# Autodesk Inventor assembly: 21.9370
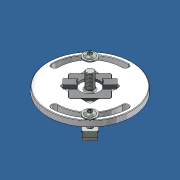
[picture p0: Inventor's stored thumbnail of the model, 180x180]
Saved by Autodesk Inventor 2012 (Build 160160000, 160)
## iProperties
Created: 2013-05
Part Number: 21.9370
Document SubType Name: Assembly
Designer: Admin
Description: PIVOT FASTENER 45
Author: Admin
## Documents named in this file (6)
- C:\Andys Backup Data\ANDY'S INVENTOR\INVENTOR LIBRARIES\PARTS LIBRARY\FASTENING ELEMENTS\21.9370 PIVOT FASTENER 45.iam
- C:\Andys Backup Data\ANDY'S INVENTOR\INVENTOR LIBRARIES\PARTS LIBRARY\FASTENING ELEMENTS\SUBCOMPONENTS\21.2016 ANTI TWIST.ipt
- C:\Andys Backup Data\ANDY'S INVENTOR\INVENTOR LIBRARIES\PARTS LIBRARY\FASTENING ELEMENTS\BUTTON HEAD FLANGE SCREWS\21.9965 M6X20 BUTTON HEAD FLANGE.ipt
- C:\Andys Backup Data\ANDY'S INVENTOR\INVENTOR LIBRARIES\PARTS LIBRARY\FASTENING ELEMENTS\NUTS\21.1330_2 M6 SQUARE NUT POS FXG.ipt
- C:\Andys Backup Data\ANDY'S INVENTOR\INVENTOR LIBRARIES\PARTS LIBRARY\FASTENING ELEMENTS\SUBCOMPONENTS\21.9370_1 PIVOT FASTENER 45.ipt
- C:\Andys Backup Data\ANDY'S INVENTOR\INVENTOR LIBRARIES\PARTS LIBRARY\FASTENING ELEMENTS\SCREWS COUNTERSUNK\21.1514 M8X20 CSUNK.IPT
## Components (7 placed, 5 different names)
1. 21.9370_1 PIVOT FASTENER 45:1 — Flush:1, Mate:1, Mate:2, Flush:2, Mate:5, Mate:6, Mate:12, Mate:13, Mate:14, Mate:15, Angle:4
2. 21.2016 ANTI TWIST:1 — Flush:1, Mate:1, Angle:2, Angle:3, Angle:4, Mate:17
3. 21.1514 M8x20 C'SUNK:1 — Mate:2, Flush:2
4. 21.9965 M6X20 BUTTON HEAD FLANGE:1 — Mate:5, Mate:9, Mate:12
5. 21.9965 M6X20 BUTTON HEAD FLANGE:2 — Mate:6, Mate:11, Mate:13, Mate:16, Mate:17
6. 21.1330_2 M6 SQUARE NUT POS FXG:1 — Mate:9, Mate:15, Angle:3, Mate:16
7. 21.1330_2 M6 SQUARE NUT POS FXG:2 — Mate:11, Angle:2, Mate:14
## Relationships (17: Mate 12, Angle 3, Flush 2)
- Flush:1: 21.9370_1 PIVOT FASTENER 45:1 ↔ 21.2016 ANTI TWIST:1
- Mate:1: 21.9370_1 PIVOT FASTENER 45:1 ↔ 21.2016 ANTI TWIST:1
- Mate:2: 21.9370_1 PIVOT FASTENER 45:1 ↔ 21.1514 M8x20 C'SUNK:1
- Flush:2: 21.9370_1 PIVOT FASTENER 45:1 ↔ 21.1514 M8x20 C'SUNK:1
- Mate:5: 21.9370_1 PIVOT FASTENER 45:1 ↔ 21.9965 M6X20 BUTTON HEAD FLANGE:1
- Mate:6: 21.9370_1 PIVOT FASTENER 45:1 ↔ 21.9965 M6X20 BUTTON HEAD FLANGE:2
- Mate:9: 21.9965 M6X20 BUTTON HEAD FLANGE:1 ↔ 21.1330_2 M6 SQUARE NUT POS FXG:1
- Mate:11: 21.9965 M6X20 BUTTON HEAD FLANGE:2 ↔ 21.1330_2 M6 SQUARE NUT POS FXG:2
- Angle:2: 21.2016 ANTI TWIST:1 ↔ 21.1330_2 M6 SQUARE NUT POS FXG:2
- Mate:12: 21.9370_1 PIVOT FASTENER 45:1 ↔ 21.9965 M6X20 BUTTON HEAD FLANGE:1
- Mate:13: 21.9370_1 PIVOT FASTENER 45:1 ↔ 21.9965 M6X20 BUTTON HEAD FLANGE:2
- Mate:14: 21.9370_1 PIVOT FASTENER 45:1 ↔ 21.1330_2 M6 SQUARE NUT POS FXG:2
- Mate:15: 21.9370_1 PIVOT FASTENER 45:1 ↔ 21.1330_2 M6 SQUARE NUT POS FXG:1
- Angle:3: 21.2016 ANTI TWIST:1 ↔ 21.1330_2 M6 SQUARE NUT POS FXG:1
- Mate:16: 21.9965 M6X20 BUTTON HEAD FLANGE:2 ↔ 21.1330_2 M6 SQUARE NUT POS FXG:1
- Angle:4: 21.9370_1 PIVOT FASTENER 45:1 ↔ 21.2016 ANTI TWIST:1
- Mate:17: 21.2016 ANTI TWIST:1 ↔ 21.9965 M6X20 BUTTON HEAD FLANGE:2
